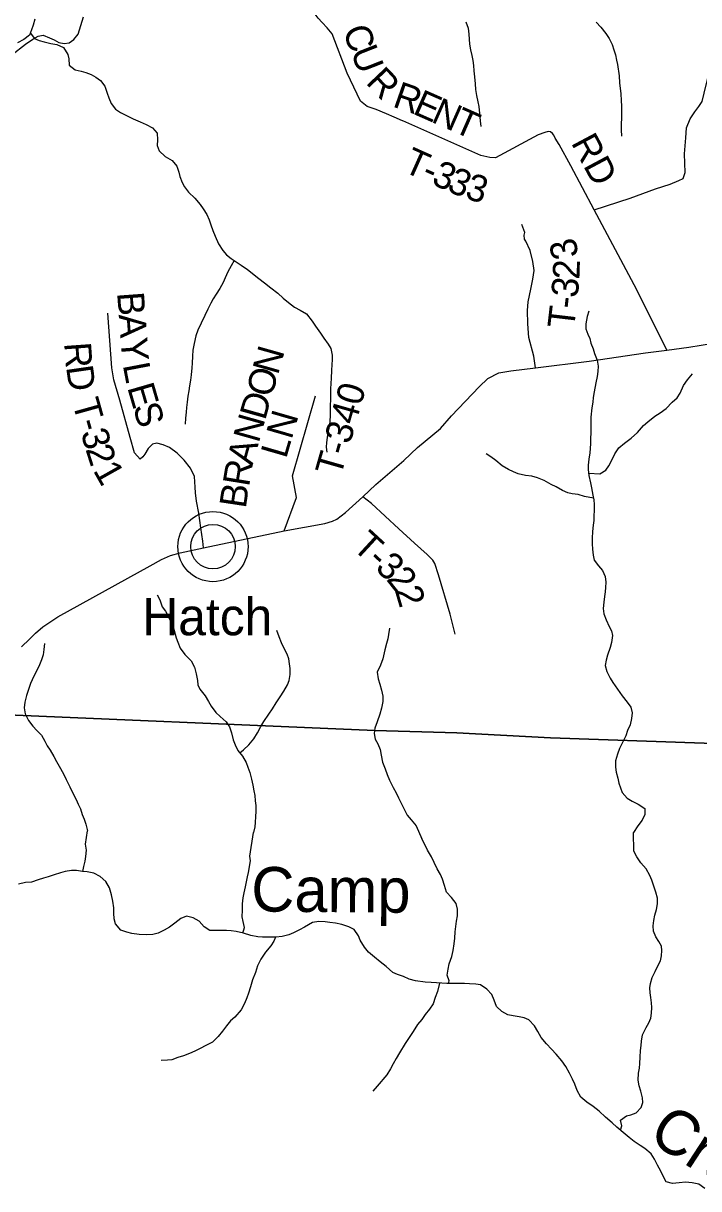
# Model space of a CAD drawing. Extents: x 1578669 to 1989827, y 208020 to 553079.
# Drawn here: x 1774179 to 1781742, y 360980 to 374035 of the extents above; entities that cross this region are included whole.
import ezdxf

# ---------------------------------------------------------------- set-up
doc = ezdxf.new("R2010")
doc.units = 0
for name, color, linetype in [('GM_X_Minor_River', 7, 'Continuous'), ('GM_X_Minor_River_Text', 7, 'Continuous'), ('GM_X_State_Route', 7, 'Continuous'), ('GM_X_Township', 7, 'Continuous'), ('GM_X_Township_Road', 7, 'Continuous'), ('GM_X_Township_Road_Text', 7, 'Continuous'), ('GM_X_Unincorporated', 7, 'Continuous'), ('GM_X_Unincorporated_Location', 7, 'Continuous'), ('GM_X_Unincorporated_Text', 7, 'Continuous')]:
    doc.layers.add(name, color=color, linetype=linetype)

msp = doc.modelspace()

# ---------------------------------------------------------------- linework, layer by layer
at = {"layer": 'GM_X_Minor_River'}
for points in [[(1774308, 374083), (1774290, 374013), (1774272, 373962), (1774248, 373904), (1774184, 373853), (1774114, 373817)], [(1779136, 374053), (1779160, 373981), (1779168, 373915), (1779172, 373857), (1779177, 373802), (1779187, 373740), (1779203, 373674), (1779213, 373620), (1779221, 373562), (1779224, 373504), (1779230, 373435), (1779238, 373357), (1779244, 373295), (1779253, 373227), (1779269, 373157), (1779279, 373103), (1779289, 373024), (1779296, 372944), (1779304, 372880)], [(1780595, 374048), (1780645, 373992), (1780703, 373922), (1780740, 373864), (1780772, 373799), (1780792, 373739)], [(1774257, 373927), (1774306, 373866), (1774358, 373842), (1774411, 373828), (1774487, 373811), (1774555, 373799), (1774629, 373763), (1774677, 373687), (1774689, 373636), (1774694, 373568), (1774758, 373516), (1774826, 373500), (1774880, 373486), (1774940, 373461), (1774992, 373433), (1775043, 373395), (1775091, 373333), (1775119, 373254), (1775137, 373202), (1775164, 373138), (1775212, 373072), (1775266, 373037), (1775334, 373001), (1775410, 372967), (1775487, 372932), (1775555, 372902), (1775625, 372864), (1775677, 372804), (1775681, 372731), (1775676, 372665), (1775700, 372605), (1775766, 372545), (1775844, 372498), (1775899, 372434), (1775919, 372368), (1775931, 372318), (1775959, 372253), (1775983, 372203), (1776030, 372143), (1776098, 372077), (1776158, 372006), (1776192, 371956), (1776233, 371892), (1776261, 371832), (1776279, 371779), (1776301, 371713), (1776326, 371649), (1776366, 371565), (1776414, 371492), (1776456, 371442), (1776508, 371400), (1776561, 371364), (1776619, 371327), (1776691, 371279), (1776815, 371178), (1776880, 371128), (1776950, 371072), (1777030, 371011), (1777090, 370955), (1777147, 370909), (1777215, 370856), (1777279, 370822), (1777349, 370780), (1777412, 370697), (1777452, 370643), (1777508, 370565), (1777544, 370509), (1777591, 370442), (1777623, 370392), (1777639, 370318), (1777637, 370264), (1777635, 370214), (1777630, 370147), (1777626, 370059), (1777622, 369999), (1777618, 369939), (1777617, 369636), (1777613, 369586), (1777606, 369532), (1777594, 369468), (1777580, 369394), (1777574, 369338), (1777572, 369286), (1777577, 369232)], [(1780792, 373739), (1780810, 373683), (1780823, 373623), (1780833, 373573), (1780851, 373446), (1780857, 373370), (1780870, 373244), (1780874, 373172), (1780878, 373109), (1780876, 373041), (1780875, 372841), (1780879, 372771)], [(1776540, 371378), (1776505, 371320), (1776471, 371252), (1776441, 371184), (1776417, 371132), (1776380, 371064), (1776340, 371002), (1776306, 370949), (1776278, 370899), (1776244, 370833), (1776210, 370763), (1776171, 370675), (1776135, 370597), (1776111, 370533), (1776091, 370449), (1776078, 370375), (1776072, 370305), (1776068, 370229), (1776066, 370177), (1776060, 370098), (1776051, 370036), (1776039, 369976), (1776031, 369920), (1776023, 369858), (1776015, 369790), (1776006, 369730), (1776002, 369680), (1775996, 369612), (1775990, 369545)], [(1780512, 370809), (1780493, 370751), (1780478, 370667), (1780478, 370613), (1780501, 370554), (1780523, 370504), (1780536, 370454), (1780562, 370387), (1780577, 370335), (1780606, 370263), (1780616, 370193), (1780613, 370136), (1780606, 370080), (1780590, 370006), (1780571, 369906), (1780562, 369842), (1780555, 369792), (1780547, 369728), (1780534, 369624), (1780533, 369504), (1780534, 369446), (1780531, 369386), (1780531, 369328), (1780526, 369274), (1780522, 369222), (1780513, 369154), (1780506, 369086), (1780506, 369036), (1780513, 368971), (1780530, 368887), (1780540, 368831), (1780557, 368749), (1780566, 368696), (1780572, 368644), (1780573, 368578), (1780568, 368518), (1780566, 368466), (1780559, 368414), (1780553, 368342), (1780550, 368268), (1780549, 368206), (1780553, 368145), (1780560, 368079), (1780573, 368021), (1780619, 367957), (1780664, 367904), (1780696, 367840), (1780701, 367775), (1780698, 367715), (1780696, 367665), (1780689, 367613), (1780681, 367549), (1780674, 367481), (1780679, 367419), (1780705, 367353), (1780738, 367278), (1780765, 367228), (1780777, 367176), (1780766, 367100), (1780749, 367042), (1780721, 366956), (1780706, 366900), (1780695, 366840), (1780713, 366773), (1780750, 366701), (1780779, 366651), (1780833, 366576), (1780884, 366501), (1780941, 366431), (1780983, 366376), (1780996, 366310), (1780991, 366248), (1780973, 366176), (1780946, 366112), (1780925, 366054), (1780886, 365970), (1780856, 365913), (1780831, 365847), (1780812, 365775), (1780812, 365701), (1780819, 365648), (1780836, 365578), (1780848, 365522), (1780865, 365472), (1780885, 365419), (1780942, 365355), (1780998, 365320), (1781065, 365287), (1781139, 365241), (1781138, 365171), (1781108, 365109), (1781061, 365045), (1781012, 364969)], [(1780510, 368995), (1780635, 368988), (1780702, 369028), (1780734, 369079), (1780775, 369155), (1780803, 369211), (1780846, 369279), (1780911, 369332), (1780987, 369388), (1781056, 369453), (1781123, 369529), (1781173, 369572), (1781250, 369633), (1781310, 369673), (1781376, 369720), (1781445, 369790), (1781500, 369841), (1781534, 369893), (1781573, 369977), (1781618, 370043), (1781674, 370108)], [(1780563, 368714), (1780463, 368735), (1780391, 368756), (1780327, 368765), (1780275, 368777), (1780217, 368800), (1780146, 368843), (1780090, 368867), (1780013, 368914), (1779937, 368945), (1779875, 368961), (1779803, 368970), (1779722, 368989), (1779668, 369010), (1779614, 369036), (1779543, 369079), (1779471, 369136), (1779416, 369178), (1779362, 369213)], [(1775679, 367631), (1775707, 367575), (1775734, 367500), (1775771, 367450), (1775805, 367387), (1775828, 367337), (1775854, 367287), (1775869, 367233), (1775892, 367152), (1775910, 367102), (1775937, 367034), (1775986, 366963), (1776060, 366892), (1776097, 366824), (1776116, 366749), (1776129, 366675), (1776135, 366625), (1776154, 366575), (1776216, 366502), (1776253, 366439), (1776284, 366385), (1776334, 366316), (1776385, 366270), (1776451, 366209), (1776486, 366153), (1776511, 366086), (1776530, 366010), (1776550, 365952), (1776583, 365889), (1776635, 365825), (1776674, 365756), (1776695, 365704), (1776717, 365644), (1776736, 365569), (1776749, 365499), (1776761, 365437), (1776772, 365383), (1776775, 365324), (1776781, 365274), (1776782, 365206), (1776780, 365148), (1776777, 365084), (1776770, 365034), (1776758, 364970)], [(1778279, 367260), (1778270, 367190), (1778261, 367140), (1778247, 367088), (1778228, 367016), (1778205, 366916), (1778178, 366844), (1778142, 366766), (1778153, 366692), (1778172, 366632), (1778191, 366563), (1778205, 366497), (1778206, 366439), (1778191, 366365), (1778171, 366295), (1778142, 366211), (1778117, 366139), (1778107, 366081), (1778120, 366017), (1778149, 365963), (1778175, 365900), (1778188, 365836), (1778203, 365760), (1778231, 365683), (1778254, 365619), (1778279, 365557), (1778320, 365476), (1778354, 365416), (1778381, 365359), (1778416, 365285), (1778452, 365216), (1778479, 365164), (1778521, 365111), (1778578, 365045), (1778641, 364898)], [(1776605, 365862), (1776645, 365895), (1776706, 365952), (1776762, 366020), (1776803, 366088), (1776838, 366159), (1776872, 366213), (1776929, 366297), (1776968, 366355), (1777010, 366422), (1777055, 366490), (1777096, 366552), (1777138, 366623), (1777157, 366675), (1777166, 366741), (1777166, 366807), (1777161, 366860), (1777151, 366916), (1777132, 366968), (1777101, 367030), (1777071, 367095), (1777044, 367161), (1777017, 367234)], [(1774415, 367087), (1774409, 367019), (1774400, 366961), (1774382, 366905), (1774360, 366847), (1774328, 366777), (1774296, 366723), (1774261, 366639), (1774237, 366573), (1774215, 366504), (1774197, 366430), (1774189, 366366), (1774198, 366298), (1774238, 366226), (1774286, 366163), (1774332, 366113), (1774381, 366061), (1774419, 365995), (1774447, 365942), (1774479, 365892), (1774521, 365822), (1774550, 365766), (1774594, 365687), (1774634, 365619), (1774660, 365563), (1774701, 365481), (1774729, 365420), (1774769, 365340), (1774793, 365286), (1774818, 365234), (1774838, 365172), (1774860, 365119), (1774878, 365065), (1774897, 364989)], [(1774845, 364535), (1774856, 364591), (1774872, 364651), (1774879, 364701), (1774885, 364771), (1774874, 364841), (1774897, 364989)], [(1776639, 363844), (1776656, 363906), (1776642, 363973), (1776631, 364025), (1776632, 364101), (1776634, 364173), (1776641, 364239), (1776653, 364295), (1776668, 364363), (1776678, 364417), (1776689, 364473), (1776701, 364523), (1776722, 364654), (1776717, 364704), (1776758, 364970)], [(1778940, 363278), (1778946, 363310), (1778926, 363372), (1778935, 363440), (1778947, 363498), (1778976, 363580), (1778994, 363648), (1779003, 363724), (1779010, 363786), (1779016, 363857), (1779021, 363919), (1779031, 363977), (1779042, 364037), (1779042, 364111), (1779027, 364175), (1778973, 364242), (1778918, 364303), (1778894, 364375), (1778873, 364447), (1778849, 364498), (1778814, 364564), (1778780, 364633), (1778749, 364699), (1778706, 364772), (1778674, 364836), (1778641, 364898)], [(1780865, 361635), (1780880, 361683), (1780867, 361748), (1780933, 361795), (1780983, 361807), (1781040, 361831), (1781096, 361888), (1781117, 361946), (1781113, 361998), (1781094, 362073), (1781076, 362131), (1781065, 362197), (1781069, 362273), (1781078, 362332), (1781084, 362384), (1781087, 362454), (1781092, 362530), (1781098, 362584), (1781102, 362634), (1781113, 362702), (1781154, 362786), (1781182, 362838), (1781205, 362890), (1781215, 362948), (1781218, 363010), (1781214, 363062), (1781207, 363121), (1781197, 363173), (1781196, 363229), (1781202, 363279), (1781221, 363347), (1781255, 363413), (1781286, 363475), (1781314, 363533), (1781327, 363587), (1781331, 363647), (1781324, 363697), (1781296, 363749), (1781262, 363802), (1781235, 363864), (1781233, 363924), (1781238, 363984), (1781252, 364045), (1781269, 364109), (1781282, 364173), (1781280, 364235), (1781261, 364301), (1781243, 364359), (1781218, 364438), (1781196, 364490), (1781155, 364563), (1781095, 364629), (1781048, 364698), (1781014, 364762), (1781012, 364969)], [(1775167, 364271), (1775144, 364350), (1775102, 364420), (1775041, 364477), (1774969, 364514), (1774893, 364528), (1774843, 364535), (1774773, 364545), (1774717, 364544), (1774647, 364532), (1774597, 364519), (1774524, 364497), (1774456, 364474), (1774406, 364458), (1774346, 364441), (1774272, 364413), (1774203, 364410), (1774125, 364392)], [(1781019, 361510), (1780965, 361552), (1780896, 361609), (1780826, 361668), (1780774, 361718), (1780699, 361783), (1780627, 361848), (1780560, 361901), (1780490, 361951), (1780424, 362006), (1780381, 362079), (1780354, 362151), (1780328, 362207), (1780297, 362276), (1780253, 362348), (1780210, 362411), (1780146, 362486), (1780095, 362542), (1780039, 362603), (1779979, 362674), (1779942, 362740), (1779902, 362805), (1779841, 362871), (1779789, 362896), (1779733, 362906), (1779663, 362917), (1779603, 362927), (1779537, 362964), (1779478, 363021), (1779450, 363091), (1779425, 363157), (1779371, 363216), (1779298, 363263), (1779246, 363271), (1779176, 363276), (1779120, 363280), (1779053, 363279), (1778985, 363279), (1778921, 363278), (1778867, 363282), (1778805, 363287), (1778745, 363289), (1778679, 363294), (1778571, 363307), (1778501, 363329), (1778435, 363356), (1778371, 363379), (1778318, 363403), (1778242, 363468), (1778174, 363521), (1778111, 363573), (1778043, 363630), (1777998, 363685), (1777950, 363763), (1777931, 363813), (1777883, 363884), (1777825, 363915), (1777745, 363941), (1777674, 363956), (1777612, 363964), (1777560, 363971), (1777487, 363974), (1777417, 363964), (1777329, 363911), (1777272, 363879), (1777206, 363848), (1777152, 363824), (1777078, 363804), (1777007, 363799), (1776929, 363798), (1776859, 363796), (1776807, 363801), (1776727, 363817), (1776645, 363842), (1776561, 363861), (1776507, 363869), (1776455, 363872), (1776403, 363872), (1776339, 363871), (1776267, 363871), (1776205, 363914), (1776150, 363977), (1776080, 364013), (1776006, 364032), (1775944, 364006), (1775877, 363953), (1775815, 363909), (1775757, 363878), (1775690, 363842), (1775630, 363826), (1775554, 363825), (1775476, 363826), (1775396, 363838), (1775340, 363855), (1775270, 363878), (1775211, 363946), (1775195, 364003), (1775194, 364067), (1775194, 364125), (1775183, 364201), (1775167, 364271)], [(1777003, 363799), (1776983, 363753), (1776951, 363701), (1776892, 363630), (1776837, 363552), (1776800, 363476), (1776778, 363402), (1776747, 363318), (1776724, 363242), (1776700, 363172), (1776683, 363120), (1776657, 363056), (1776618, 362984), (1776549, 362903), (1776499, 362859), (1776456, 362803), (1776410, 362743), (1776361, 362684), (1776297, 362620), (1776224, 362584), (1776160, 362549), (1776098, 362519), (1776039, 362496), (1775973, 362468), (1775911, 362451), (1775843, 362423), (1775792, 362420), (1775722, 362418)], [(1778839, 363284), (1778818, 363190), (1778792, 363121), (1778767, 363051), (1778727, 362991), (1778678, 362931), (1778642, 362875), (1778595, 362819), (1778544, 362742), (1778506, 362684), (1778455, 362606), (1778390, 362502), (1778354, 362440), (1778321, 362379), (1778291, 362323), (1778248, 362257), (1778143, 362127), (1778092, 362074)], [(1781809, 360982), (1781742, 361031), (1781668, 361045), (1781596, 361052), (1781524, 361046), (1781448, 361037), (1781378, 361056), (1781344, 361120), (1781318, 361175), (1781279, 361243), (1781248, 361311), (1781210, 361372), (1781138, 361431), (1781087, 361465), (1781019, 361510)]]:
    msp.add_lwpolyline(points, dxfattribs=at)
at = {"layer": 'GM_X_State_Route'}
msp.add_lwpolyline([(1774160, 367049), (1774248, 367136), (1774316, 367203), (1774396, 367276), (1774566, 367385), (1775599, 367958), (1775726, 368029), (1775828, 368074), (1775934, 368104), (1776195, 368159), (1777100, 368348), (1777554, 368433), (1777643, 368457), (1777689, 368479), (1777785, 368555), (1777982, 368732), (1778126, 368869), (1778440, 369137), (1778593, 369283), (1778850, 369498), (1778975, 369638), (1779283, 369962), (1779380, 370057), (1779503, 370120), (1779640, 370143), (1779914, 370176), (1780515, 370251), (1781148, 370345), (1781385, 370375), (1781631, 370407), (1782047, 370474)], dxfattribs=at)
at = {"layer": 'GM_X_Township'}
for points in [[(1786899, 381582), (1786521, 373852), (1786434, 371261), (1786221, 365919), (1786212, 365818), (1783765, 365903), (1783641, 365911), (1782725, 365930), (1781802, 365972), (1780082, 366031), (1779034, 366088), (1778117, 366114), (1773560, 366308), (1773026, 366323), (1772094, 366350), (1770384, 366431), (1768021, 366509), (1765116, 366648), (1759075, 366898)], [(1759075, 366898), (1765116, 366648), (1768021, 366509), (1770384, 366431), (1772094, 366350), (1773026, 366323), (1773560, 366308), (1778117, 366114), (1779034, 366088), (1780082, 366031), (1781802, 365972), (1782725, 365930), (1783641, 365911), (1783765, 365903), (1786212, 365818), (1786429, 365785), (1788628, 365490), (1790140, 365259), (1790672, 365179), (1791051, 365124), (1793209, 364816), (1795322, 364551), (1813574, 362259)]]:
    msp.add_lwpolyline(points, dxfattribs=at)
at = {"layer": 'GM_X_Township_Road'}
for points in [[(1778429, 372943), (1778427, 372944), (1778333, 372985), (1778246, 373022), (1778132, 373071), (1778030, 373105), (1777953, 373164), (1777804, 373475), (1777639, 373918), (1777580, 373985), (1777524, 374044), (1777479, 374092), (1777449, 374137), (1777398, 374424)], [(1774049, 373681), (1774203, 373801), (1774286, 373857), (1774344, 373892), (1774401, 373904), (1774473, 373871), (1774524, 373850), (1774576, 373821), (1774638, 373810), (1774693, 373818), (1774745, 373855), (1774792, 373913), (1774854, 374109)], [(1780571, 371944), (1780973, 372075), (1781258, 372181), (1781421, 372233), (1781519, 372274), (1781570, 372297), (1781590, 372363), (1781583, 372574), (1781597, 372753), (1781606, 372863), (1781647, 372965), (1781698, 373044), (1781744, 373102), (1781781, 373158), (1781804, 373254), (1781840, 373406), (1781869, 373558), (1781925, 373712), (1782002, 373812), (1782108, 373929), (1782175, 374014), (1782223, 374074)], [(1781385, 370375), (1781048, 371049), (1780571, 371944), (1780309, 372438), (1780181, 372677), (1780134, 372749), (1780120, 372784), (1780104, 372800), (1780082, 372818), (1780058, 372823), (1780018, 372811), (1779944, 372786), (1779467, 372530), (1779405, 372531), (1779301, 372556), (1778429, 372943)], [(1779914, 370176), (1779897, 370305), (1779839, 370514), (1779827, 370667), (1779825, 370817), (1779832, 370914), (1779861, 371058), (1779885, 371170), (1779898, 371266), (1779885, 371367), (1779856, 371492), (1779805, 371593), (1779791, 371617), (1779788, 371661), (1779796, 371693), (1779761, 371780)], [(1776195, 368159), (1776189, 368234), (1776166, 368385), (1776144, 368549), (1776120, 368684), (1776107, 368776), (1776103, 368839), (1776095, 368959), (1776050, 369050), (1775980, 369141), (1775901, 369219), (1775817, 369282), (1775746, 369315), (1775674, 369332), (1775627, 369320), (1775577, 369274), (1775538, 369209), (1775517, 369179), (1775489, 369151), (1775424, 369224), (1775377, 369397), (1775258, 369812), (1775194, 370040), (1775171, 370177), (1775125, 370790)], [(1777100, 368348), (1777237, 368724), (1777194, 368966), (1777452, 369864)], [(1779016, 367191), (1778958, 367418), (1778829, 367857), (1778788, 367985), (1778766, 368020), (1778700, 368083), (1778560, 368211), (1778385, 368371), (1778077, 368656), (1777982, 368732)]]:
    msp.add_lwpolyline(points, dxfattribs=at)
at = {"layer": 'GM_X_Unincorporated'}
for radius in [393, 249]:
    msp.add_circle((1776303, 368173), radius, dxfattribs=at)
at = {"layer": 'GM_X_Unincorporated_Location'}
msp.add_line((1776303, 368173), (1776303, 368173), dxfattribs=at)

# ---------------------------------------------------------------- texts
at = {"layer": 'GM_X_Minor_River_Text'}
for s, rotation, p in [('Camp', 359.504, (1776730, 364086)), ('Creek', 326.8717, (1781158, 361534))]:
    msp.add_text(s, height=500, rotation=rotation, dxfattribs=at).set_placement(p)
at = {"layer": 'GM_X_Township_Road_Text'}
for s, rotation, p in [('C', 290.1495, (1777752, 373957)), ('U', 291.4557, (1777840, 373719)), ('R', 313.584, (1778004, 373367)), ('R', 340.7242, (1778303, 373106)), ('E', 336.1768, (1778529, 373027)), ('N', 336.1777, (1778735, 372936)), ('T', 336.2266, (1778977, 372829)), ('RD', 298.1027, (1780308, 372698)), ('T', 335.9004, (1778418, 372381)), ('3', 336.1538, (1778737, 372239)), ('-', 335.9619, (1778624, 372289)), ('3', 336.9152, (1778910, 372162)), ('3', 343.0238, (1779113, 372078)), ('3', 103.2799, (1780403, 371432)), ('2', 88.2609, (1780406, 371162)), ('3', 84.0703, (1780385, 370954)), ('B', 274.2386, (1775229, 371017)), ('-', 83.4786, (1780371, 370829)), ('A', 274.2367, (1775247, 370771)), ('T', 83.3555, (1780345, 370605)), ('Y', 274.4358, (1775267, 370507)), ('R', 274.1682, (1774636, 370453)), ('N', 74.2369, (1777030, 370087)), ('D', 278.1208, (1774657, 370185)), ('L', 280.8013, (1775292, 370208)), ('O', 74.2369, (1776958, 369833)), ('E', 286.2237, (1775341, 369957)), ('T-340', 74.0549, (1777732, 368947)), ('T', 285.5987, (1774725, 369789)), ('D', 74.2327, (1776886, 369579)), ('S', 286.134, (1775404, 369742)), ('N', 74.2362, (1776814, 369325)), ('LN', 73.8414, (1777121, 369150)), ('3', 286.0497, (1774820, 369452)), ('-', 285.677, (1774786, 369572)), ('2', 287.5668, (1774873, 369266)), ('A', 74.5315, (1776744, 369071)), ('1', 299.2857, (1774955, 369028)), ('R', 80.5826, (1776706, 368836)), ('B', 81.4084, (1776669, 368593)), ('T', 317.3613, (1777852, 368157)), ('-', 317.4049, (1778017, 368005)), ('3', 317.6188, (1778108, 367921)), ('2', 308.2949, (1778236, 367805)), ('2', 286.3907, (1778337, 367687))]:
    msp.add_text(s, height=300, rotation=rotation, dxfattribs=at).set_placement(p)
at = {"layer": 'GM_X_Unincorporated_Text'}
msp.add_text('Hatch', height=417, rotation=0, dxfattribs=at).set_placement((1775511, 367180))

doc.saveas('drawing.dxf')
